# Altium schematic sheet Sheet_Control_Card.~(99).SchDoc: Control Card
size A4; Date: 05/05/2013; ApprovedBy: Vincenzo Niespolo; CheckedBy: Vincenzo Niespolo; Author: Vincenzo Niespolo; CompanyName: NiespoTech; DrawnBy: Vincenzo Niespolo; Engineer: Vincenzo Niespolo; Organization: NiespoTech; Address1: Viale E. De Amicis n°39; Address2: Imola (BO); Address3: Cell. +39 334 9113322; Address4: e-mail: niespotech@gmail.com; DocumentNumber: 1; Revision: 00; SheetNumber: 1; SheetTotal: 5
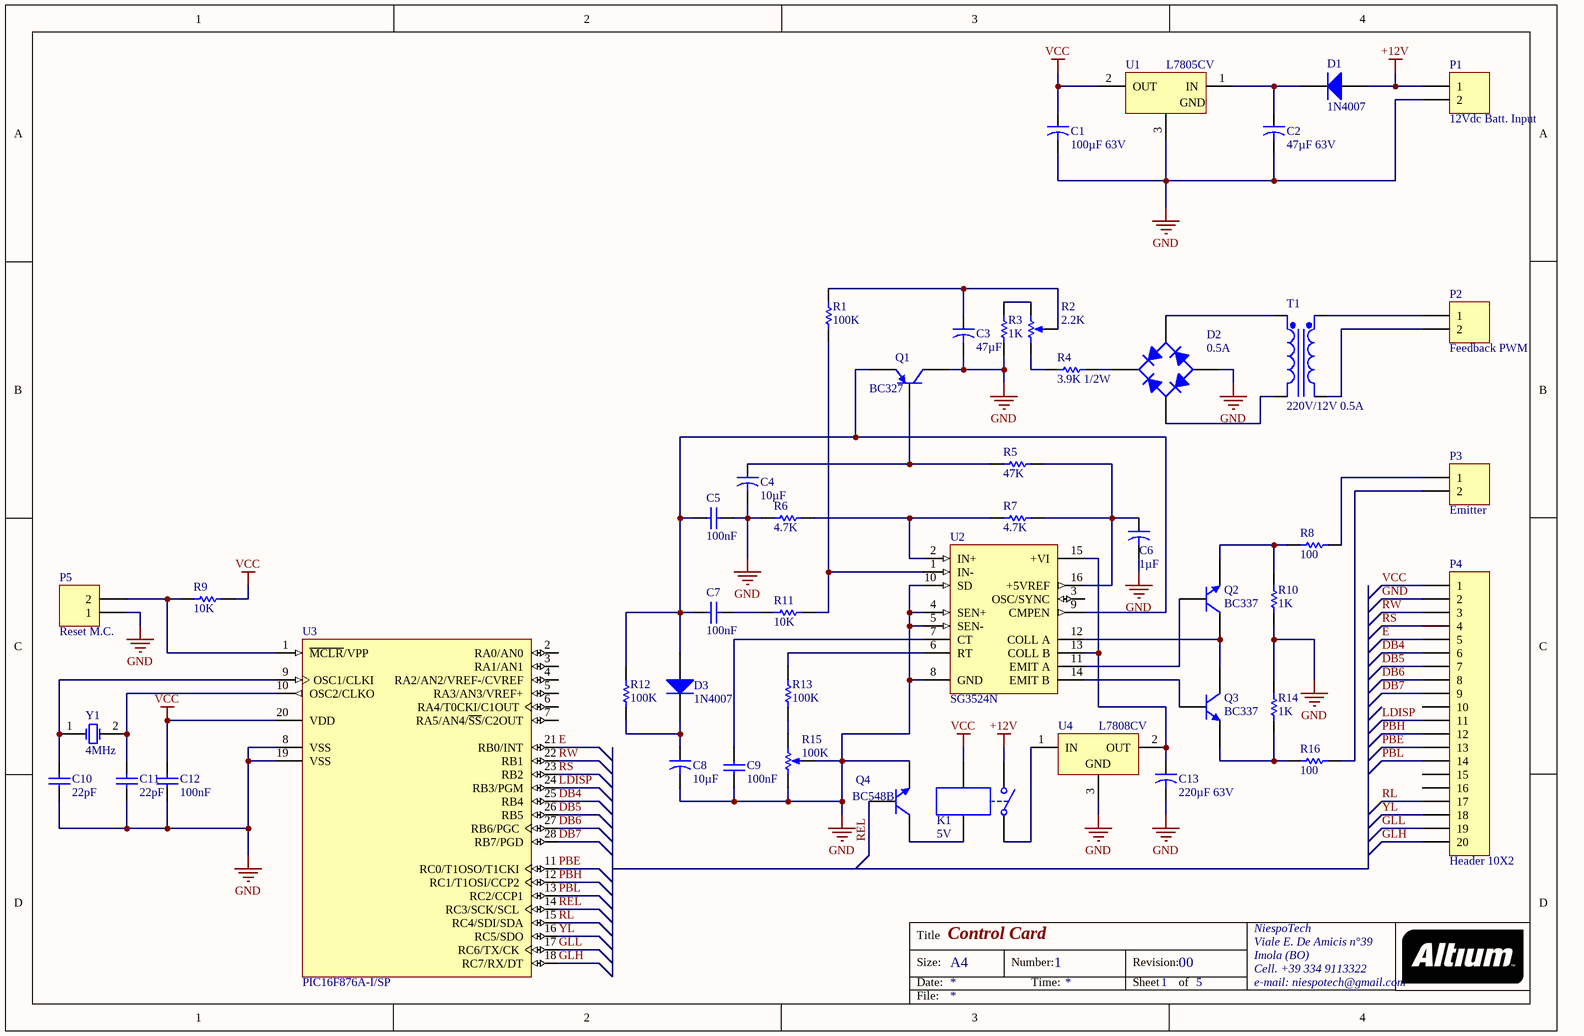
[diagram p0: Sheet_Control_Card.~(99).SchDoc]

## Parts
C1  100µF 63V  [CAPR5-4X5]
C2  47µF 63V  [CAPR5-4X5]
C3  47µF  [CAPR5-4X5]
C4  10µF  [CAPR5-4X5]
C5  100nF  [RAD-0.3]
C6  1µF  [CAPR5-4X5]
C7  100nF  [RAD-0.3]
C8  10µF  [CAPR5-4X5]
C9  100nF  [RAD-0.3]
C10  22pF  [RAD-0.3]
C11  22pF  [RAD-0.3]
C12  100nF  [RAD-0.3]
C13  220µF 63V  [CAPR5-4X5]
D1  1N4007  [DO-41]
D2  0.5A  [D-38]
D3  1N4007  [DO-41]
K1  5V  [MODULE4]
P1  12Vdc Batt. Input  [HDR1X2]
P2  Feedback PWM  [HDR1X2]
P3  Emitter  [HDR1X2]
P4  Header 10X2  [HDR2X10_CEN]
P5  Reset M.C.  [HDR1X2H]
Q1  BC327  [29-04]
Q2  BC337  [SOT54]
Q3  BC337  [SOT54]
Q4  BC548B  [29-04]
R1  100K  [AXIAL-0.3]
R2  2.2K  [VR5]
R3  1K  [AXIAL-0.3]
R4  3.9K 1/2W  [AXIAL-0.3]
R5  47K  [AXIAL-0.3]
R6  4.7K  [AXIAL-0.3]
R7  4.7K  [AXIAL-0.3]
R8  100  [AXIAL-0.3]
R9  10K  [AXIAL-0.3]
R10  1K  [AXIAL-0.3]
R11  10K  [AXIAL-0.3]
R12  100K  [AXIAL-0.3]
R13  100K  [AXIAL-0.3]
R14  1K  [AXIAL-0.3]
R15  100K  [VR5]
R16  100  [AXIAL-0.3]
T1  220V/12V 0.5A  [TRF_4]
U1  L7805CV  [TO220ABN]
U2  SG3524N  [DIP16]
U3  PIC16F876A-I/SP  [SPDIP300-SP28]
U4  L7808CV  [TO220ABN]
Y1  4MHz  [R38]

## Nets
+12V: D1.1(A) K1.2 P1.1
GND: C1.2 C2.2 C3.2 C4.2 C5.1 C6.2 C8.2 C9.1 C10.1 C11.1 C12.1 C13.2 D2.3(A) P1.2 P4.2 P5.1 Q1.1(C) Q4.3(E) R3.1 R6.1 R10.1 R14.2 R15.1(TOP) R15.3(TAP) U1.3(GND) U2.4(SEN+) U2.5(SEN-) U2.8(GND) U2.10(SD) U3.8(VSS) U3.19(VSS) U4.3(GND)
VCC: C1.1 C12.2 K1.4 P4.1 R9.2 U1.2(OUT) U3.20(VDD)
DB4: P4.6 U3.25(RB4)
DB5: P4.7 U3.26(RB5)
DB6: P4.8 U3.27(RB6/PGC)
DB7: P4.9 U3.28(RB7/PGD)
E: P4.5 U3.21(RB0/INT)
GLH: P4.20 U3.18(RC7/RX/DT)
GLL: P4.19 U3.17(RC6/TX/CK)
LDISP: P4.11 U3.24(RB3/PGM)
PBE: P4.13 U3.11(RC0/T1OSO/T1CKI)
PBH: P4.12 U3.12(RC1/T1OSI/CCP2)
PBL: P4.14 U3.13(RC2/CCP1)
REL: Q4.2(B) U3.14(RC3/SCK/SCL)
RL: P4.17 U3.15(RC4/SDI/SDA)
RS: P4.4 U3.23(RB2)
RW: P4.3 U3.22(RB1)
YL: P4.18 U3.16(RC5/SDO)
NetC2_1: C2.1 D1.2(K) U1.1(IN)
NetC3_1: C3.1 R1.2 R2.3(TAP)
NetC4_1: C4.1 Q1.2(B) R5.2
NetC5_2: C5.2 C7.2 D3.1(A) Q1.3(E) R12.2 U2.9(CMPEN)
NetC6_1: C6.1 R5.1 R7.2 U2.16(+5VREF)
NetC7_1: C7.1 R11.2
NetC8_1: C8.1 D3.2(K) R12.1
NetC9_2: C9.2 U2.7(CT)
NetC10_2: C10.2 U3.9(OSC1/CLKI) Y1.1(OSC1)
NetC11_2: C11.2 U3.10(OSC2/CLKO) Y1.2(OSC2)
NetC13_1: C13.1 U2.13(COLL_B) U2.15(+VI) U4.2(OUT)
NetD2_1: D2.1(K) R4.2
NetD2_2: D2.2(C) T1.4(Sec-)
NetD2_4: D2.4(C) T1.3(Sec+)
NetK1_1: K1.1 U4.1(IN)
NetK1_3: K1.3 Q4.1(C)
NetP2_1: P2.1 T1.1(Pri+)
NetP2_2: P2.2 T1.2(Pri-)
NetP3_1: P3.1 R8.1
NetP3_2: P3.2 R16.1
NetP5_2: P5.2 R9.1 U3.1(~{MCLR}/VPP)
NetQ2_1: Q2.1(E) R8.2 R10.2
NetQ2_2: Q2.2(B) U2.11(EMIT_A)
NetQ2_3: Q2.3(C) Q3.3(C) U2.12(COLL_A)
NetQ3_1: Q3.1(E) R14.1 R16.2
NetQ3_2: Q3.2(B) U2.14(EMIT_B)
NetR1_1: R1.1 R11.1 U2.1(IN-)
NetR2_1: R2.1(TOP) R4.1
NetR2_2: R2.2(BOT) R3.2
NetR6_2: R6.2 R7.1 U2.2(IN+)
NetR13_1: R13.1 R15.2(BOT)
NetR13_2: R13.2 U2.6(RT)

Not connected (* = marked no-connect by the designer): P4 10 15 16; U2 3(OSC/SYNC); U3 2(RA0/AN0) 3(RA1/AN1) 4(RA2/AN2/VREF-/CVREF) 5(RA3/AN3/VREF+) 6(RA4/T0CKI/C1OUT) 7(RA5/AN4/~{SS}/C2OUT)

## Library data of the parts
C1-C4 C6 C8 C13 = Cap2: Capacitor
C5 C7 C9-C12 = Cap: Capacitor
D1 D3 = Diode 1N4007: 1 Amp General Purpose Rectifier
D2 = Bridge1: Full Wave Diode Bridge
K1 = Relay-SPST: Single-Pole Single-Throw Relay
P1-P3 = Header 2: Header, 2-Pin
P4 = Header 20: Header, 20-Pin
P5 = Header 2H: Header, 2-Pin, Right Angle
Q1 = BC327-16: Amplifier Transistor PNP Silicon
Q2 Q3 = BC337: NPN General-purpose Transistor
Q4 = BC548B: Amplifier Transistor NPN Silicon
R1 R3-R14 R16 = Res1: Resistor
R2 R15 = RPot: Potentiometer; Sim Note: Enter the Resistance value and the set point into parameter fields.; Set Position: 0.5
T1 = Trans Ideal: Transformer (Ideal)
U1 = L7805CV: Positive Voltage Regulator; Note: Tab is connected to pin 3 (GND).
U2 = SG3524N: Regulating Pulse Width Modulator
U3 = PIC16F876A-I/SP: Enhanced FLASH Microcontroller, 8K (x14-Bit words) FLASH, 368 Bytes RAM, 28-Pin PDIP 300mil, Standard VDD Range, Industrial Temperature; ComponentAvailability: Unknown. Contact manufacturer to determine status.
U4 = L7808CV: Positive Voltage Regulator; Note: Tab is connected to pin 3 (GND).
Y1 = XTAL: Crystal Oscillator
